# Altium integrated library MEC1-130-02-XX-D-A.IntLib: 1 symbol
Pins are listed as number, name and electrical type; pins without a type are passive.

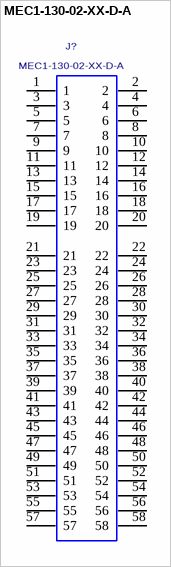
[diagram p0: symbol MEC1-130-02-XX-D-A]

## MEC1-130-02-XX-D-A
designator J?
1MM MIN-EDGE CARD ASSEMBLY.; MANUFACTURER: SAMTEC
footprint MEC1-130-02-XX-D-A
pins: 1, 2, 3, 4, 5, 6, 7, 8, 9, 10, 11, 12, 13, 14, 15, 16, 17, 18, 19, 20, 21, 22, 23, 24, 25, 26, 27, 28, 29, 30, 31, 32, 33, 34, 35, 36, 37, 38, 39, 40, 41, 42, 43, 44, 45, 46, 47, 48, 49, 50, 51, 52, 53, 54, 55, 56, 57, 58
